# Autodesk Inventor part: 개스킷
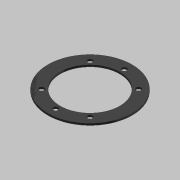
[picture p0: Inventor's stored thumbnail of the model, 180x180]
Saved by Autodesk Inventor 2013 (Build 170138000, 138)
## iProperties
Created: 2018-06
Part Number: 개스킷
Material: 고무
Document SubType Name: Modeling
Designer: G4400
Density: 1 g/cm^3
Author: G4400
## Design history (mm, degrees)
sketch "스케치1"
  geometry: C1 r 32.5 at (0, 0); C2 r 23 at (0, 0); 1 further point
  constraints: 2 centre point, 2 coincident
  dimensions: "d0" = 65 diameter of C1; "d1" = 46 diameter of C2
extrude "돌출1" new body sketch "스케치1" distance "d2" = 1.5; taper "d3" = 0 deg
sketch "스케치2" dims "d5" = 26.5
  geometry: C1 r 23 at (0, 0) reference; C2 r 32.5 at (0, 0) reference; 2 further points
  constraints: 2 vertical alignment, 1 coincident, 2 other
hole "구멍1" sketch "스케치2" at (0, 26.5) diameter "d11" = 4; stored, may be unused: countersink angle "d15" = 90 deg, drill point angle "d17" = 118 deg; dims "d12" = 6, "d13" = 4, "d14" = 2, "d16" = 8
node "솔리드1"
pattern_circular "원형 패턴1" dims angle "d19" = 360 deg
